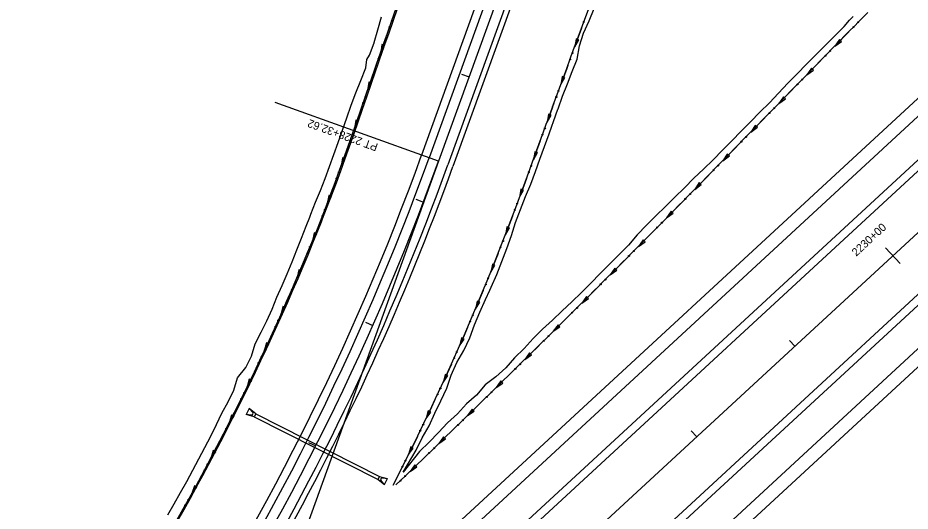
# Model space of a CAD drawing. Extents: x 1611108 to 1749517, y 619561 to 797725.
# Drawn here: x 1726972 to 1727641, y 771673 to 772043 of the extents above; entities that cross this region are included whole.
import ezdxf

# ---------------------------------------------------------------- set-up
doc = ezdxf.new("R2010")
doc.units = 0
for name, color, linetype in [('R_Ditch', 7, 'Continuous'), ('R_Drainage', 7, 'Continuous'), ('R_Horz Alg', 7, 'Continuous'), ('R_Horz Alg Annot', 7, 'Continuous'), ('R_Horz Alg Stationing', 7, 'Continuous'), ('R_Proposed Const Limits', 7, 'Continuous'), ('R_Proposed Road', 7, 'Continuous')]:
    doc.layers.add(name, color=color, linetype=linetype)

msp = doc.modelspace()

# ---------------------------------------------------------------- linework, layer by layer
at = {"layer": 'R_Ditch'}
for p, q in [((1727244.96, 772023.28), (1727244, 772017.26)), ((1727244, 772017.26), (1727246.96, 772022.59)), ((1727246.96, 772022.59), (1727244.96, 772023.28)), ((1727390.39, 772027.45), (1727389.33, 772021.45)), ((1727389.33, 772021.45), (1727392.38, 772026.72)), ((1727392.38, 772026.72), (1727390.39, 772027.45)), ((1727587.65, 772027.02), (1727584.22, 772021.99)), ((1727584.22, 772021.99), (1727589.17, 772025.54)), ((1727589.17, 772025.54), (1727587.65, 772027.02)), ((1727566.66, 772005.53), (1727563.23, 772000.5)), ((1727563.23, 772000.5), (1727568.18, 772004.05)), ((1727568.18, 772004.05), (1727566.66, 772005.53)), ((1727380.08, 771999.24), (1727379.01, 771993.24)), ((1727379.01, 771993.24), (1727382.06, 771998.51)), ((1727382.06, 771998.51), (1727380.08, 771999.24)), ((1727235.16, 771994.89), (1727234.2, 771988.87)), ((1727234.2, 771988.87), (1727237.16, 771994.2)), ((1727237.16, 771994.2), (1727235.16, 771994.89)), ((1727545.67, 771984.04), (1727542.24, 771979.01)), ((1727542.24, 771979.01), (1727547.19, 771982.56)), ((1727547.19, 771982.56), (1727545.67, 771984.04)), ((1727369.76, 771971.03), (1727368.69, 771965.03)), ((1727368.69, 771965.03), (1727371.75, 771970.3)), ((1727371.75, 771970.3), (1727369.76, 771971.03)), ((1727225.35, 771966.49), (1727224.39, 771960.48)), ((1727224.39, 771960.48), (1727227.35, 771965.8)), ((1727227.35, 771965.8), (1727225.35, 771966.49)), ((1727524.68, 771962.56), (1727521.25, 771957.52)), ((1727526.2, 771961.08), (1727524.68, 771962.56)), ((1727521.25, 771957.52), (1727526.2, 771961.08)), ((1727359.44, 771942.82), (1727358.37, 771936.82)), ((1727358.37, 771936.82), (1727361.43, 771942.09)), ((1727361.43, 771942.09), (1727359.44, 771942.82)), ((1727215.44, 771938.16), (1727214.4, 771932.15)), ((1727214.4, 771932.15), (1727217.43, 771937.44)), ((1727217.43, 771937.44), (1727215.44, 771938.16)), ((1727503.69, 771941.07), (1727500.26, 771936.04)), ((1727500.26, 771936.04), (1727505.21, 771939.59)), ((1727505.21, 771939.59), (1727503.69, 771941.07)), ((1727482.69, 771919.6), (1727479.25, 771914.57)), ((1727479.25, 771914.57), (1727484.2, 771918.11)), ((1727484.2, 771918.11), (1727482.69, 771919.6)), ((1727205.08, 771909.98), (1727203.95, 771903.99)), ((1727203.95, 771903.99), (1727207.06, 771909.23)), ((1727207.06, 771909.23), (1727205.08, 771909.98)), ((1727349.12, 771914.61), (1727348.05, 771908.61)), ((1727348.05, 771908.61), (1727351.11, 771913.88)), ((1727351.11, 771913.88), (1727349.12, 771914.61)), ((1727461.64, 771898.18), (1727458.18, 771893.16)), ((1727458.18, 771893.16), (1727463.14, 771896.69)), ((1727463.14, 771896.69), (1727461.64, 771898.18)), ((1727194.2, 771882.01), (1727192.92, 771876.05)), ((1727196.16, 771881.21), (1727194.2, 771882.01)), ((1727338.61, 771886.49), (1727337.46, 771880.51)), ((1727337.46, 771880.51), (1727340.59, 771885.73)), ((1727340.59, 771885.73), (1727338.61, 771886.49)), ((1727192.92, 771876.05), (1727196.16, 771881.21)), ((1727440.53, 771876.81), (1727437.05, 771871.81)), ((1727437.05, 771871.81), (1727442.03, 771875.32)), ((1727442.03, 771875.32), (1727440.53, 771876.81)), ((1727327.68, 771858.53), (1727326.43, 771852.56)), ((1727326.43, 771852.56), (1727329.64, 771857.74)), ((1727329.64, 771857.74), (1727327.68, 771858.53)), ((1727419.36, 771855.51), (1727415.87, 771850.51)), ((1727420.86, 771854.01), (1727419.36, 771855.51)), ((1727182.71, 771854.28), (1727181.33, 771848.34)), ((1727181.33, 771848.34), (1727184.65, 771853.45)), ((1727184.65, 771853.45), (1727182.71, 771854.28)), ((1727415.87, 771850.51), (1727420.86, 771854.01)), ((1727316.31, 771830.74), (1727314.96, 771824.8)), ((1727314.96, 771824.8), (1727318.26, 771829.92)), ((1727318.26, 771829.92), (1727316.31, 771830.74)), ((1727398.13, 771834.26), (1727394.63, 771829.27)), ((1727394.63, 771829.27), (1727399.62, 771832.76)), ((1727399.62, 771832.76), (1727398.13, 771834.26)), ((1727170.76, 771826.73), (1727169.29, 771820.82)), ((1727169.29, 771820.82), (1727172.69, 771825.87)), ((1727172.69, 771825.87), (1727170.76, 771826.73)), ((1727376.85, 771813.06), (1727373.33, 771808.09)), ((1727373.33, 771808.09), (1727378.34, 771811.56)), ((1727378.34, 771811.56), (1727376.85, 771813.06)), ((1727304.5, 771803.15), (1727303.05, 771797.23)), ((1727303.05, 771797.23), (1727306.43, 771802.3)), ((1727306.43, 771802.3), (1727304.5, 771803.15)), ((1727158.37, 771799.39), (1727156.81, 771793.5)), ((1727156.81, 771793.5), (1727160.29, 771798.5)), ((1727160.29, 771798.5), (1727158.37, 771799.39)), ((1727355.5, 771791.93), (1727351.98, 771786.96)), ((1727351.98, 771786.96), (1727356.99, 771790.42)), ((1727356.99, 771790.42), (1727355.5, 771791.93)), ((1727292.26, 771775.73), (1727290.73, 771769.83)), ((1727290.73, 771769.83), (1727294.19, 771774.85)), ((1727294.19, 771774.85), (1727292.26, 771775.73)), ((1727145.53, 771772.25), (1727143.88, 771766.39)), ((1727143.88, 771766.39), (1727147.44, 771771.33)), ((1727147.44, 771771.33), (1727145.53, 771772.25)), ((1727334.11, 771770.85), (1727330.57, 771765.9)), ((1727330.57, 771765.9), (1727335.59, 771769.34)), ((1727335.59, 771769.34), (1727334.11, 771770.85)), ((1727279.62, 771748.5), (1727277.99, 771742.63)), ((1727281.53, 771747.59), (1727279.62, 771748.5)), ((1727312.65, 771749.83), (1727309.1, 771744.89)), ((1727309.1, 771744.89), (1727314.13, 771748.32)), ((1727314.13, 771748.32), (1727312.65, 771749.83)), ((1727132.27, 771745.32), (1727130.5, 771739.5)), ((1727130.5, 771739.5), (1727134.16, 771744.37)), ((1727134.16, 771744.37), (1727132.27, 771745.32)), ((1727277.99, 771742.63), (1727281.53, 771747.59)), ((1727291.14, 771728.87), (1727287.57, 771723.93)), ((1727292.61, 771727.35), (1727291.14, 771728.87)), ((1727266.55, 771721.47), (1727264.84, 771715.63)), ((1727268.45, 771720.53), (1727266.55, 771721.47)), ((1727287.57, 771723.93), (1727292.61, 771727.35)), ((1727118.55, 771718.62), (1727116.69, 771712.82)), ((1727116.69, 771712.82), (1727120.42, 771717.63)), ((1727120.42, 771717.63), (1727118.55, 771718.62)), ((1727264.84, 771715.63), (1727268.45, 771720.53)), ((1727269.57, 771707.97), (1727265.99, 771703.04)), ((1727271.04, 771706.45), (1727269.57, 771707.97)), ((1727265.99, 771703.04), (1727271.04, 771706.45)), ((1727104.4, 771692.14), (1727102.45, 771686.37)), ((1727102.45, 771686.37), (1727106.26, 771691.13)), ((1727106.26, 771691.13), (1727104.4, 771692.14))]:
    msp.add_line(p, q, dxfattribs=at)
for points in [[(1727091.36, 771666.46), (1727096.09, 771674.88), (1727100.78, 771683.33), (1727105.42, 771691.8), (1727110.02, 771700.29), (1727114.57, 771708.81), (1727119.08, 771717.35), (1727123.54, 771725.91), (1727127.96, 771734.5), (1727132.33, 771743.11), (1727136.66, 771751.74), (1727140.94, 771760.4), (1727145.18, 771769.07), (1727149.37, 771777.77), (1727153.51, 771786.49), (1727157.61, 771795.23), (1727161.66, 771804), (1727165.67, 771812.78), (1727169.63, 771821.58), (1727173.55, 771830.41), (1727177.42, 771839.25), (1727181.24, 771848.12), (1727185.01, 771857), (1727188.74, 771865.9), (1727192.42, 771874.83), (1727196.06, 771883.77), (1727198.8, 771890.59), (1727199.63, 771892.73), (1727203.1, 771901.74), (1727206.52, 771910.77), (1727209.89, 771919.81), (1727213.21, 771928.87), (1727216.49, 771937.94), (1727219.72, 771947.04), (1727222.9, 771956.14), (1727226.13, 771965.51), (1727229.39, 771974.96), (1727232.66, 771984.42), (1727235.92, 771993.87), (1727239.19, 772003.32), (1727241.2, 772009.16), (1727242.45, 772012.77), (1727245.63, 772021.97), (1727245.72, 772022.23), (1727249, 772031.67), (1727252.29, 772041.12), (1727255.57, 772050.56)], [(1727091.98, 771666.11), (1727096.72, 771674.53), (1727101.41, 771682.97), (1727106.07, 771691.44), (1727110.67, 771699.93), (1727115.23, 771708.45), (1727119.75, 771716.99), (1727124.22, 771725.55), (1727128.65, 771734.14), (1727133.03, 771742.75), (1727137.37, 771751.38), (1727141.66, 771760.04), (1727145.91, 771768.71), (1727150.11, 771777.41), (1727154.27, 771786.13), (1727158.37, 771794.87), (1727162.44, 771803.64), (1727166.46, 771812.42), (1727170.43, 771821.22), (1727174.35, 771830.05), (1727178.23, 771838.89), (1727182.06, 771847.76), (1727185.85, 771856.64), (1727189.59, 771865.55), (1727193.28, 771874.47), (1727196.92, 771883.41), (1727199.67, 771890.24), (1727200.5, 771892.38), (1727203.98, 771901.39), (1727207.41, 771910.42), (1727210.79, 771919.46), (1727214.13, 771928.52), (1727217.41, 771937.6), (1727220.65, 771946.69), (1727223.84, 771955.8), (1727227.09, 771965.16), (1727230.36, 771974.61), (1727233.63, 771984.06), (1727236.9, 771993.51), (1727240.18, 772002.97), (1727242.2, 772008.81), (1727243.45, 772012.42), (1727246.63, 772021.61), (1727246.72, 772021.87), (1727250.02, 772031.31), (1727253.31, 772040.75), (1727256.6, 772050.19)], [(1727253.32, 771692.78), (1727258.01, 771702), (1727262.66, 771711.24), (1727267.25, 771720.5), (1727271.8, 771729.79), (1727276.3, 771739.1), (1727280.75, 771748.43), (1727285.16, 771757.79), (1727289.51, 771767.17), (1727293.82, 771776.58), (1727298.07, 771786.01), (1727302.28, 771795.46), (1727306.43, 771804.93), (1727310.54, 771814.42), (1727314.6, 771823.94), (1727318.61, 771833.48), (1727321.63, 771840.76), (1727322.56, 771843.04), (1727326.46, 771852.62), (1727330.3, 771862.23), (1727334.09, 771871.85), (1727337.84, 771881.5), (1727341.53, 771891.16), (1727345.17, 771900.85), (1727348.76, 771910.55), (1727352.23, 771920.03), (1727355.67, 771929.42), (1727359.1, 771938.81), (1727362.54, 771948.2), (1727365.97, 771957.59), (1727368.09, 771963.4), (1727369.41, 771966.99), (1727372.75, 771976.12), (1727372.84, 771976.38), (1727376.28, 771985.77), (1727379.71, 771995.16), (1727383.15, 772004.55), (1727386.58, 772013.94), (1727390.02, 772023.34), (1727393.45, 772032.73), (1727396.89, 772042.12), (1727400.32, 772051.51)], [(1727608.85, 772047.2), (1727601.85, 772040.04), (1727599.18, 772037.3), (1727594.85, 772032.87), (1727566.87, 772004.22)], [(1727394.48, 772035.54), (1727393.45, 772032.73), (1727390.02, 772023.34), (1727389.33, 772021.45)], [(1727394.49, 772035.58), (1727394.48, 772035.54)], [(1727248.92, 772031.44), (1727245.72, 772022.23), (1727245.63, 772021.97), (1727244, 772017.26)], [(1727248.93, 772031.47), (1727248.92, 772031.44)], [(1727594.7, 772032.72), (1727584.22, 772021.99)], [(1727594.73, 772032.74), (1727594.7, 772032.72)], [(1727573.71, 772011.23), (1727566.87, 772004.22), (1727563.23, 772000.5)], [(1727573.74, 772011.26), (1727573.71, 772011.23)], [(1727239.09, 772003.05), (1727235.92, 771993.87), (1727234.2, 771988.87)], [(1727239.11, 772003.09), (1727239.09, 772003.05)], [(1727566.87, 772004.22), (1727559.87, 771997.06), (1727552.87, 771989.9), (1727545.88, 771982.74), (1727538.88, 771975.57), (1727531.88, 771968.41), (1727524.89, 771961.25), (1727517.89, 771954.09), (1727510.89, 771946.92), (1727503.89, 771939.76), (1727496.9, 771932.6), (1727489.9, 771925.44), (1727482.89, 771918.29), (1727475.88, 771911.14), (1727468.86, 771904), (1727461.83, 771896.87), (1727454.8, 771889.74), (1727447.77, 771882.62), (1727440.73, 771875.51), (1727433.68, 771868.4), (1727426.62, 771861.3), (1727419.56, 771854.21), (1727412.49, 771847.12), (1727405.42, 771840.04), (1727398.34, 771832.97), (1727391.25, 771825.9), (1727384.16, 771818.84), (1727377.06, 771811.79), (1727369.96, 771804.74), (1727362.85, 771797.7), (1727355.73, 771790.67), (1727348.61, 771783.64), (1727341.48, 771776.62), (1727334.35, 771769.61), (1727327.21, 771762.6), (1727320.06, 771755.6), (1727312.91, 771748.61), (1727305.75, 771741.62), (1727298.58, 771734.64), (1727291.41, 771727.66), (1727284.24, 771720.7), (1727277.05, 771713.74), (1727269.86, 771706.78), (1727262.67, 771699.83), (1727255.47, 771692.89)], [(1727384.16, 772007.33), (1727383.15, 772004.55), (1727379.71, 771995.16), (1727379.01, 771993.24)], [(1727384.17, 772007.37), (1727384.16, 772007.33)], [(1727552.72, 771989.74), (1727545.88, 771982.74), (1727542.24, 771979.01)], [(1727552.75, 771989.77), (1727552.72, 771989.74)], [(1727373.84, 771979.12), (1727372.84, 771976.38), (1727372.75, 771976.12), (1727369.41, 771966.99), (1727368.69, 771965.03)], [(1727373.86, 771979.16), (1727373.84, 771979.12)], [(1727229.29, 771974.66), (1727226.13, 771965.51), (1727224.39, 771960.48)], [(1727229.3, 771974.69), (1727229.29, 771974.66)], [(1727531.73, 771968.25), (1727524.89, 771961.25), (1727521.25, 771957.52)], [(1727531.76, 771968.28), (1727531.73, 771968.26)], [(1727363.53, 771950.91), (1727362.54, 771948.2), (1727359.1, 771938.81), (1727358.37, 771936.82)], [(1727363.54, 771950.95), (1727363.53, 771950.91)], [(1727219.45, 771946.28), (1727216.49, 771937.94), (1727214.4, 771932.15)], [(1727219.46, 771946.31), (1727219.45, 771946.28)], [(1727510.74, 771946.77), (1727503.89, 771939.76), (1727500.26, 771936.04)], [(1727510.77, 771946.79), (1727510.74, 771946.77)], [(1727353.21, 771922.7), (1727352.23, 771920.03), (1727348.76, 771910.55), (1727348.05, 771908.62)], [(1727353.22, 771922.74), (1727353.21, 771922.7)], [(1727489.75, 771925.28), (1727482.89, 771918.29), (1727479.25, 771914.57)], [(1727489.77, 771925.31), (1727489.75, 771925.28)], [(1727209.22, 771918.03), (1727206.52, 771910.77), (1727203.95, 771903.99)], [(1727209.24, 771918.07), (1727209.22, 771918.03)], [(1727468.71, 771903.84), (1727461.83, 771896.87), (1727458.18, 771893.16)], [(1727468.73, 771903.87), (1727468.71, 771903.85)], [(1727198.54, 771889.96), (1727196.06, 771883.77), (1727192.92, 771876.05)], [(1727198.56, 771889.99), (1727198.54, 771889.96)], [(1727342.79, 771894.52), (1727341.53, 771891.16), (1727337.84, 771881.5), (1727337.45, 771880.51)], [(1727342.81, 771894.56), (1727342.79, 771894.53)], [(1727447.61, 771882.46), (1727440.73, 771875.51), (1727437.05, 771871.81)], [(1727447.64, 771882.49), (1727447.61, 771882.46)], [(1727187.17, 771862.16), (1727185.01, 771857), (1727181.33, 771848.34)], [(1727187.19, 771862.19), (1727187.17, 771862.16)], [(1727331.98, 771866.5), (1727330.3, 771862.23), (1727326.46, 771852.62), (1727326.43, 771852.56)], [(1727332, 771866.53), (1727331.98, 771866.5)], [(1727426.46, 771861.14), (1727419.56, 771854.21), (1727415.87, 771850.51)], [(1727426.48, 771861.16), (1727426.46, 771861.14)], [(1727320.75, 771838.64), (1727318.61, 771833.48), (1727314.96, 771824.8)], [(1727320.76, 771838.68), (1727320.75, 771838.64)], [(1727405.24, 771839.87), (1727398.34, 771832.97), (1727394.63, 771829.27)], [(1727405.27, 771839.9), (1727405.24, 771839.87)], [(1727175.36, 771834.54), (1727173.55, 771830.41), (1727169.63, 771821.58), (1727169.29, 771820.82)], [(1727175.37, 771834.58), (1727175.36, 771834.54)], [(1727383.97, 771818.66), (1727377.06, 771811.79), (1727373.33, 771808.09)], [(1727384, 771818.68), (1727383.97, 771818.66)], [(1727309.05, 771810.98), (1727306.43, 771804.93), (1727303.05, 771797.23)], [(1727309.07, 771811.01), (1727309.05, 771810.98)], [(1727163.09, 771807.12), (1727161.66, 771804), (1727157.61, 771795.23), (1727156.8, 771793.5)], [(1727163.11, 771807.16), (1727163.09, 771807.12)], [(1727362.65, 771797.5), (1727355.73, 771790.67), (1727351.98, 771786.96)], [(1727362.68, 771797.53), (1727362.65, 771797.5)], [(1727296.93, 771783.49), (1727293.82, 771776.58), (1727290.73, 771769.83)], [(1727296.95, 771783.53), (1727296.93, 771783.49)], [(1727150.38, 771779.9), (1727149.37, 771777.77), (1727145.18, 771769.07), (1727143.87, 771766.39)], [(1727150.4, 771779.94), (1727150.38, 771779.9)], [(1727341.27, 771776.41), (1727334.35, 771769.61), (1727330.57, 771765.9)], [(1727341.29, 771776.43), (1727341.27, 771776.41)], [(1727284.4, 771756.19), (1727280.75, 771748.43), (1727277.99, 771742.63)], [(1727284.42, 771756.23), (1727284.4, 771756.19)], [(1727319.83, 771755.37), (1727312.91, 771748.61), (1727309.1, 771744.89)], [(1727319.85, 771755.4), (1727319.83, 771755.37)], [(1727137.23, 771752.9), (1727136.66, 771751.74), (1727132.33, 771743.11), (1727130.5, 771739.5)], [(1727137.25, 771752.93), (1727137.23, 771752.9)], [(1727298.36, 771734.42), (1727298.33, 771734.39)], [(1727271.46, 771729.09), (1727267.25, 771720.5), (1727264.84, 771715.63)], [(1727271.48, 771729.12), (1727271.46, 771729.09)], [(1727298.33, 771734.39), (1727291.41, 771727.66), (1727287.57, 771723.93)], [(1727123.64, 771726.11), (1727123.54, 771725.91), (1727119.08, 771717.35), (1727116.69, 771712.82)], [(1727123.66, 771726.14), (1727123.64, 771726.11)], [(1727276.78, 771713.47), (1727269.86, 771706.78), (1727265.99, 771703.04)], [(1727276.8, 771713.49), (1727276.78, 771713.47)], [(1727258.12, 771702.22), (1727258.1, 771702.18)], [(1727109.62, 771699.55), (1727105.42, 771691.8), (1727102.45, 771686.37)], [(1727109.63, 771699.58), (1727109.62, 771699.55)], [(1727095.18, 771673.25), (1727095.16, 771673.22)]]:
    msp.add_lwpolyline(points, dxfattribs=at)
for centre in [(1727250.6, 772036.17), (1727252.25, 772040.9), (1727396.24, 772040.24), (1727598.24, 772036.28), (1727601.74, 772039.87), (1727387.64, 772016.74), (1727580.75, 772018.38), (1727242.4, 772012.52), (1727385.92, 772012.03), (1727577.25, 772014.8), (1727240.77, 772007.78), (1727559.76, 771996.89), (1727377.32, 771988.53), (1727556.26, 771993.31), (1727232.6, 771984.13), (1727375.6, 771983.82), (1727230.96, 771979.39), (1727538.77, 771975.41), (1727535.26, 771971.82), (1727222.79, 771955.73), (1727365.28, 771955.61), (1727367.01, 771960.32), (1727221.14, 771951.01), (1727514.27, 771950.33), (1727517.78, 771953.92), (1727356.69, 771932.11), (1727493.28, 771928.85), (1727496.78, 771932.43), (1727211, 771922.73), (1727212.72, 771927.43), (1727354.97, 771927.4), (1727475.77, 771910.97), (1727346.34, 771903.91), (1727472.25, 771907.4), (1727200.4, 771894.63), (1727202.2, 771899.3), (1727344.6, 771899.21), (1727454.69, 771889.57), (1727451.17, 771886.01), (1727335.68, 771875.83), (1727191.05, 771871.41), (1727333.86, 771871.16), (1727433.55, 771868.23), (1727189.14, 771866.78), (1727430.02, 771864.67), (1727324.58, 771847.91), (1727179.39, 771843.73), (1727322.7, 771843.27), (1727408.82, 771843.4), (1727412.36, 771846.94), (1727177.4, 771839.13), (1727387.56, 771822.17), (1727391.11, 771825.71), (1727167.27, 771816.24), (1727311.07, 771815.57), (1727313.04, 771820.18), (1727165.21, 771811.67), (1727366.24, 771801.01), (1727369.8, 771804.54), (1727154.71, 771788.96), (1727299.02, 771788.06), (1727301.06, 771792.63), (1727152.57, 771784.42), (1727348.44, 771783.42), (1727344.87, 771779.91), (1727141.7, 771761.88), (1727288.67, 771765.27), (1727327.02, 771762.36), (1727139.49, 771757.38), (1727286.56, 771760.73), (1727323.44, 771758.86), (1727305.54, 771741.36), (1727128.26, 771735.02), (1727275.86, 771738.1), (1727301.95, 771737.87), (1727125.97, 771730.56), (1727273.68, 771733.59), (1727280.41, 771716.94), (1727284.01, 771720.42), (1727114.38, 771708.38), (1727262.64, 771711.13), (1727112.02, 771703.96), (1727260.39, 771706.65), (1727258.81, 771696.06), (1727262.41, 771699.54), (1727100.07, 771681.97), (1727097.64, 771677.59)]:
    msp.add_circle(centre, 0.375, dxfattribs=at)
at = {"layer": 'R_Drainage'}
for p, q in [((1727145.41, 771750.12), (1727143.16, 771745.66)), ((1727150.34, 771746.23), (1727145.41, 771750.12)), ((1727148.1, 771747.28), (1727145.41, 771750.12)), ((1727149.21, 771744), (1727143.16, 771745.66)), ((1727147.04, 771745.18), (1727143.16, 771745.66)), ((1727150.34, 771746.23), (1727149.21, 771744)), ((1727149.21, 771744), (1727242.03, 771697.09)), ((1727150.34, 771746.23), (1727243.16, 771699.32)), ((1727242.03, 771697.09), (1727243.16, 771699.32)), ((1727242.03, 771697.09), (1727246.95, 771693.2)), ((1727243.16, 771699.32), (1727249.21, 771697.66)), ((1727244.27, 771696.04), (1727246.95, 771693.2)), ((1727245.33, 771698.13), (1727249.21, 771697.66)), ((1727246.95, 771693.2), (1727249.21, 771697.66))]:
    msp.add_line(p, q, dxfattribs=at)
for centre, start, end in [((1727147.19, 771746.42), 263.00706, 43.36881), ((1727245.18, 771696.89), 83.00706, 223.36881)]:
    msp.add_arc(centre, 1.25, start, end, dxfattribs=at)
at = {"layer": 'R_Horz Alg'}
for p, q in [((1726122.78, 770473.69), (1737235.67, 780746.34)), ((1727518.02, 772575.19), (1727287.33, 771935.59))]:
    msp.add_line(p, q, dxfattribs=at)
msp.add_arc((1725490.76, 772583.58), 1909.86, 312.75, 340.16667, dxfattribs=at)
at = {"layer": 'R_Horz Alg Annot'}
for points in [[(1727287.33, 771935.59), (1727165.04, 771979.7)], [(1727287.33, 771935.59), (1727129.27, 771497.36), (1726787.17, 771181.13)]]:
    msp.add_lwpolyline(points, dxfattribs=at)
at = {"layer": 'R_Horz Alg Stationing'}
for points in [[(1727304.55, 772001.01), (1727310.19, 771998.97)], [(1727270.39, 771907.13), (1727276, 771905)], [(1727622.24, 771870.67), (1727633.1, 771858.92)], [(1727232.55, 771814.92), (1727238.04, 771812.5)], [(1727550.16, 771801.32), (1727554.24, 771796.91)], [(1727476.73, 771733.44), (1727480.8, 771729.03)], [(1727189.94, 771724.82), (1727195.29, 771722.11)]]:
    msp.add_lwpolyline(points, dxfattribs=at)
at = {"layer": 'R_Proposed Const Limits'}
for points in [[(1727260.86, 771702.58), (1727270.6, 771718.87), (1727275.16, 771728.18), (1727280.24, 771737.24), (1727284.45, 771746.71), (1727289, 771756.02), (1727293.53, 771765.35), (1727296.81, 771775.24), (1727301.07, 771784.68), (1727306.21, 771793.75), (1727310.73, 771803.09), (1727314.3, 771812.84), (1727318.31, 771822.39), (1727322.6, 771831.84), (1727325.83, 771839.05), (1727326.83, 771841.31), (1727330.99, 771850.81), (1727334.88, 771860.43), (1727338.44, 771870.17), (1727341.88, 771879.96), (1727345.11, 771889.82), (1727348.8, 771899.51), (1727352.59, 771909.16), (1727356.41, 771918.52), (1727359.96, 771927.87), (1727363.31, 771937.29), (1727366.76, 771946.68), (1727370.12, 771956.1), (1727372.23, 771961.91), (1727373.51, 771965.5), (1727376.78, 771974.67), (1727376.87, 771974.92), (1727380.26, 771984.33), (1727383.88, 771993.66), (1727387.5, 772002.98), (1727391.08, 772012.32), (1727393.03, 772022.25), (1727395.95, 772031.82), (1727400.31, 772040.88), (1727404.02, 772050.17)], [(1727084.46, 771670.42), (1727089.19, 771678.79), (1727093.9, 771687.17), (1727098.64, 771695.54), (1727103.25, 771703.98), (1727107.73, 771712.49), (1727112.36, 771720.92), (1727116.85, 771729.43), (1727120.95, 771738.13), (1727125.09, 771746.82), (1727129.7, 771755.26), (1727133.95, 771763.88), (1727136.81, 771773.19), (1727142.91, 771780.91), (1727147.14, 771789.55), (1727150.08, 771798.79), (1727154.51, 771807.34), (1727158.6, 771816.04), (1727162.62, 771824.77), (1727166.24, 771833.68), (1727170.11, 771842.48), (1727173.9, 771851.31), (1727177.65, 771860.16), (1727181.2, 771869.09), (1727184.72, 771878.03), (1727188.22, 771886.98), (1727190.82, 771893.83), (1727191.66, 771895.95), (1727195.18, 771904.89), (1727198.8, 771913.79), (1727202.42, 771922.69), (1727205.6, 771931.76), (1727208.82, 771940.81), (1727212.15, 771949.82), (1727215.35, 771958.88), (1727218.6, 771968.23), (1727221.9, 771977.66), (1727225.44, 771987.02), (1727229.17, 771996.3), (1727232.86, 772005.61), (1727233.71, 772011.87), (1727235.62, 772015.24), (1727239.1, 772024.33), (1727239.17, 772024.59), (1727241.78, 772034.28), (1727244.5, 772043.93)], [(1727591.25, 772036.77), (1727595.26, 772041.53), (1727597.95, 772044.25)], [(1727591.25, 772036.77), (1727563.05, 772008.35), (1727556.02, 772001.23), (1727548.92, 771994.18), (1727542.1, 771986.82), (1727535.21, 771979.54), (1727528.17, 771972.43), (1727521.14, 771965.3), (1727514.14, 771958.14), (1727507.14, 771950.98), (1727500.1, 771943.87), (1727493.06, 771936.75), (1727485.88, 771929.78), (1727478.67, 771922.86), (1727471.57, 771915.8), (1727464.49, 771908.73), (1727457.41, 771901.65), (1727450.15, 771894.78), (1727443.09, 771887.69), (1727436.26, 771880.34), (1727429.72, 771872.69), (1727422.57, 771865.68), (1727415.53, 771858.57), (1727408.52, 771851.42), (1727401.5, 771844.29), (1727394.44, 771837.19), (1727387.23, 771830.26), (1727380.01, 771823.34), (1727372.7, 771816.52), (1727365.25, 771809.83), (1727358.31, 771802.62), (1727351.57, 771795.17), (1727344.28, 771788.33), (1727337.78, 771780.63), (1727330.38, 771773.91), (1727322.34, 771767.86), (1727315.9, 771760.1), (1727308.29, 771753.6), (1727301.49, 771746.23), (1727294.14, 771739.45), (1727287.28, 771732.14), (1727280.22, 771725.04), (1727273.05, 771718.07), (1727260.86, 771702.58)]]:
    msp.add_lwpolyline(points, dxfattribs=at)
at = {"layer": 'R_Proposed Road'}
for p, q in [((1727505.32, 772579.77), (1727274.63, 771940.17)), ((1727510.97, 772577.73), (1727280.28, 771938.14)), ((1727525.08, 772572.64), (1727294.39, 771933.05)), ((1727528.84, 772571.29), (1727298.15, 771931.69)), ((1726991.58, 771377.57), (1728018.03, 772326.41)), ((1726910.49, 771288.99), (1728024.82, 772319.07)), ((1726095.63, 770503.06), (1728041.11, 772301.44)), ((1726099.71, 770498.66), (1728045.18, 772297.04)), ((1726145.86, 770448.72), (1728091.34, 772247.1)), ((1726149.94, 770444.32), (1728095.41, 772242.7)), ((1727151.11, 771337.11), (1728111.7, 772225.07)), ((1727157.9, 771329.77), (1728118.49, 772217.73))]:
    msp.add_line(p, q, dxfattribs=at)
for radius, start in [(1896.36, 312.75), (1902.36, 312.75), (1917.36, 317.64486), (1921.36, 321.22448)]:
    msp.add_arc((1725490.76, 772583.58), radius, start, 340.16667, dxfattribs=at)

# ---------------------------------------------------------------- texts
at = {"layer": 'R_Horz Alg Annot'}
msp.add_text('PT 2228+32.62', height=6, rotation=160.16667, dxfattribs=at).set_placement((1727242.45, 771948.59))
at = {"layer": 'R_Horz Alg Stationing'}
msp.add_text('2230+00', height=6, rotation=42.75, dxfattribs=at).set_placement((1727600.29, 771863.99))

doc.saveas('drawing.dxf')
